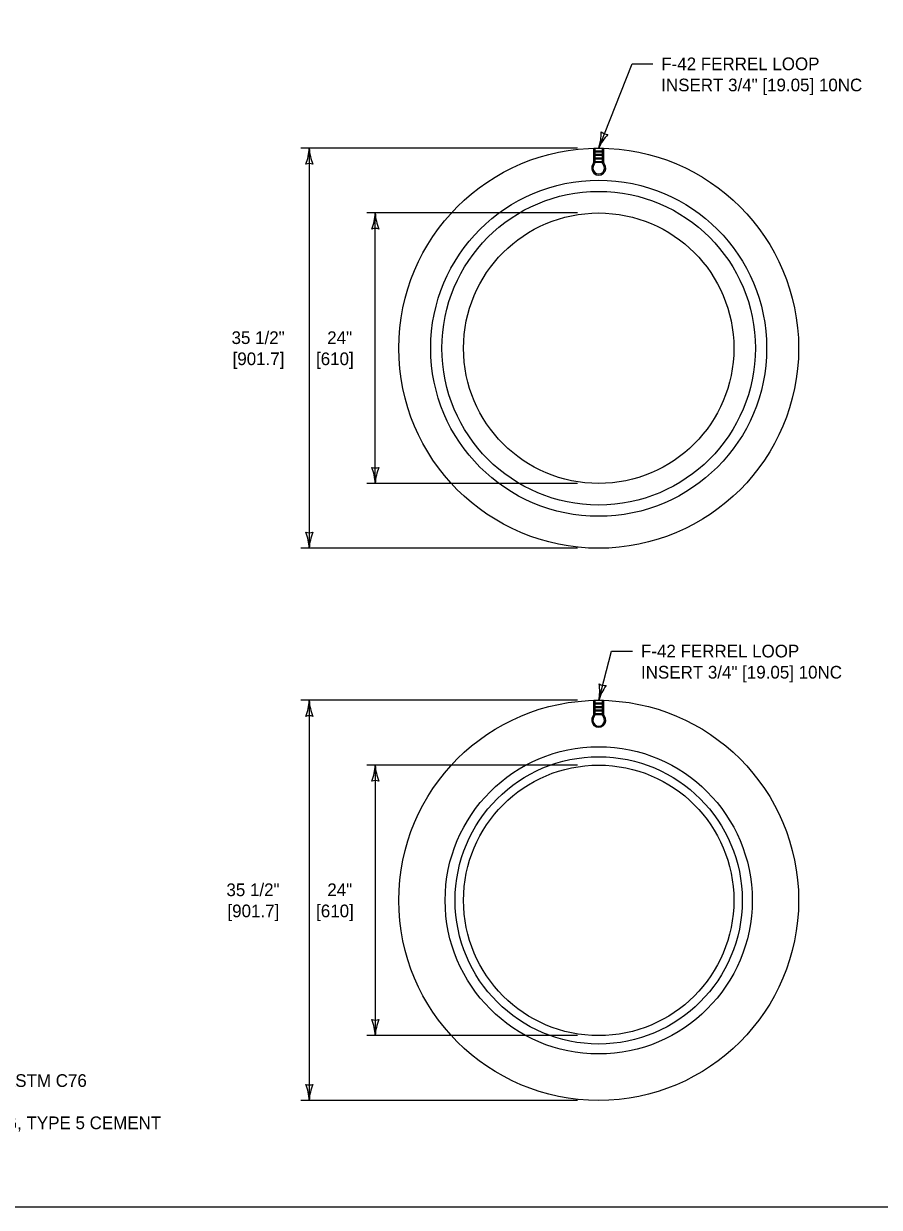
# Model space of a CAD drawing. Extents: x 49991.4 to 50021, y 49987.6 to 50011.4.
# Drawn here: x 50007.38 to 50011.44, y 49987.8 to 49993.4 of the extents above; entities that cross this region are included whole.
import ezdxf

# ---------------------------------------------------------------- set-up
doc = ezdxf.new("R2010")
doc.units = 0
for name, color, linetype in [('Level 1', 7, 'Continuous'), ('Level 2', 7, 'Continuous'), ('Level 3', 7, 'Continuous'), ('Level 4', 7, 'Continuous')]:
    doc.layers.add(name, color=color, linetype=linetype)

msp = doc.modelspace()

# ---------------------------------------------------------------- linework, layer by layer
at = {"layer": 'Level 1'}
msp.add_lwpolyline([(49999.3835, 49998.9992), (50016.7501, 49998.9992), (50016.7501, 49987.7988), (49999.3835, 49987.7988)], close=True, dxfattribs=at)
for centre, radius in [((50010.1074, 49991.8637), 0.9466), ((50010.1074, 49991.8637), 0.7953), ((50010.1074, 49991.8637), 0.7422), ((50010.1074, 49991.8637), 0.64), ((50010.1074, 49989.2512), 0.9466), ((50010.1074, 49989.2512), 0.7269), ((50010.1074, 49989.2512), 0.6798), ((50010.1074, 49989.2512), 0.64)]:
    msp.add_circle(centre, radius, dxfattribs=at)
at = {"layer": 'Level 3'}
for p, q in [((50010.0074, 49992.8104), (50008.6971, 49992.8104)), ((50008.7371, 49992.8104), (50008.7371, 49990.9171)), ((50010.0074, 49992.5037), (50009.0095, 49992.5037)), ((50009.0495, 49991.2237), (50009.0495, 49992.5037)), ((50010.0074, 49991.2237), (50009.0095, 49991.2237)), ((50010.0074, 49990.9171), (50008.6971, 49990.9171)), ((50010.0074, 49990.1978), (50008.6971, 49990.1978)), ((50008.7371, 49990.1978), (50008.7371, 49988.3045)), ((50010.0074, 49989.8912), (50009.0095, 49989.8912)), ((50009.0495, 49989.8912), (50009.0495, 49988.6112)), ((50010.0074, 49988.6112), (50009.0095, 49988.6112)), ((50010.0074, 49988.3045), (50008.6971, 49988.3045))]:
    msp.add_line(p, q, dxfattribs=at)
for points in [[(50010.1074, 49992.8104), (50010.2655, 49993.2093), (50010.3636, 49993.2093)], [(50010.1074, 49990.1978), (50010.1678, 49990.4307), (50010.2678, 49990.4307)]]:
    msp.add_lwpolyline(points, dxfattribs=at)
for centre, radius, start, end in [((50009.8868, 49992.8855), 0.233, 341.1989, 0.4487), ((50010.3105, 49992.72), 0.2223, 135.8276, 156.0111), ((50010.1546, 49992.9296), 0.0548, 230.5104, 266.2327), ((50008.5149, 49992.8196), 0.2223, 337.4389, 357.6225), ((50008.9698, 49992.8218), 0.233, 182.8102, 202.0601), ((50008.737, 49992.6822), 0.0548, 72.1218, 107.8441), ((50008.8274, 49992.513), 0.2223, 337.4389, 357.6225), ((50009.2822, 49992.5152), 0.233, 182.8102, 202.0601), ((50009.0495, 49992.3755), 0.0548, 72.1218, 107.8441), ((50009.0496, 49991.3519), 0.0548, 252.1218, 287.8441), ((50008.8168, 49991.2123), 0.233, 2.8102, 22.0601), ((50009.2717, 49991.2145), 0.2223, 157.4389, 177.6225), ((50008.7371, 49991.0453), 0.0548, 252.1218, 287.8441), ((50008.5044, 49990.9057), 0.233, 2.8102, 22.0601), ((50008.9592, 49990.9079), 0.2223, 157.4389, 177.6225), ((50009.8792, 49990.2451), 0.233, 348.2875, 7.5374), ((50010.1396, 49990.3219), 0.0548, 237.5991, 273.3214), ((50010.3201, 49990.1332), 0.2223, 142.9162, 163.0998), ((50008.5149, 49990.207), 0.2223, 337.4389, 357.6225), ((50008.9698, 49990.2092), 0.233, 182.8102, 202.0601), ((50008.737, 49990.0696), 0.0548, 72.1218, 107.8441), ((50008.8274, 49989.9004), 0.2223, 337.4389, 357.6225), ((50009.2822, 49989.9026), 0.233, 182.8102, 202.0601), ((50009.0495, 49989.763), 0.0548, 72.1218, 107.8441), ((50009.0496, 49988.7394), 0.0548, 252.1218, 287.8441), ((50008.8168, 49988.5998), 0.233, 2.8102, 22.0601), ((50009.2717, 49988.602), 0.2223, 157.4389, 177.6225), ((50008.7371, 49988.4327), 0.0548, 252.1218, 287.8441), ((50008.5044, 49988.2931), 0.233, 2.8102, 22.0601), ((50008.9592, 49988.2953), 0.2223, 157.4389, 177.6225)]:
    msp.add_arc(centre, radius, start, end, dxfattribs=at)
at = {"layer": 'Level 4'}
for p, q in [((50010.0851, 49992.748), (50010.0851, 49992.8104)), ((50010.0851, 49992.8104), (50010.1296, 49992.8104)), ((50010.0907, 49992.748), (50010.0907, 49992.8104)), ((50010.0907, 49992.7983), (50010.124, 49992.7983)), ((50010.124, 49992.8104), (50010.124, 49992.748)), ((50010.1296, 49992.8104), (50010.1296, 49992.748)), ((50010.0834, 49992.7405), (50010.084, 49992.7418)), ((50010.0886, 49992.7385), (50010.0891, 49992.7397)), ((50010.0902, 49992.7433), (50010.1245, 49992.7433)), ((50010.0907, 49992.7936), (50010.124, 49992.7936)), ((50010.0907, 49992.7815), (50010.124, 49992.7815)), ((50010.0907, 49992.7768), (50010.124, 49992.7768)), ((50010.0907, 49992.7648), (50010.124, 49992.7648)), ((50010.0907, 49992.7601), (50010.124, 49992.7601)), ((50010.0907, 49992.748), (50010.124, 49992.748)), ((50010.1261, 49992.7385), (50010.1256, 49992.7397)), ((50010.1313, 49992.7405), (50010.1308, 49992.7418)), ((50010.0851, 49990.1354), (50010.0851, 49990.1978)), ((50010.0851, 49990.1978), (50010.1296, 49990.1978)), ((50010.0907, 49990.1354), (50010.0907, 49990.1978)), ((50010.0907, 49990.1857), (50010.124, 49990.1857)), ((50010.0907, 49990.181), (50010.124, 49990.181)), ((50010.0907, 49990.169), (50010.124, 49990.169)), ((50010.0907, 49990.1643), (50010.124, 49990.1643)), ((50010.124, 49990.1978), (50010.124, 49990.1354)), ((50010.1296, 49990.1978), (50010.1296, 49990.1354)), ((50010.0834, 49990.128), (50010.084, 49990.1292)), ((50010.0886, 49990.1259), (50010.0891, 49990.1272)), ((50010.0902, 49990.1307), (50010.1245, 49990.1307)), ((50010.0907, 49990.1522), (50010.124, 49990.1522)), ((50010.0907, 49990.1475), (50010.124, 49990.1475)), ((50010.0907, 49990.1354), (50010.124, 49990.1354)), ((50010.1261, 49990.1259), (50010.1256, 49990.1272)), ((50010.1313, 49990.128), (50010.1308, 49990.1292))]:
    msp.add_line(p, q, dxfattribs=at)
for centre, radius, start, end in [((50010.068, 49992.7467), 0.0167, 321.9927, 338.1986), ((50010.0685, 49992.748), 0.0167, 338.1986, 0), ((50010.0685, 49992.748), 0.0222, 338.1986, 0), ((50010.1463, 49992.748), 0.0222, 180, 201.8014), ((50010.1463, 49992.748), 0.0167, 180, 201.8014), ((50010.1468, 49992.7467), 0.0167, 201.8014, 218.0073), ((50010.1074, 49992.7159), 0.0333, 141.9927, 38.0073), ((50010.1074, 49992.7159), 0.0278, 141.9927, 38.0073), ((50010.068, 49992.7467), 0.0222, 321.9927, 338.1986), ((50010.1468, 49992.7467), 0.0222, 201.8014, 218.0073), ((50010.1074, 49990.1034), 0.0333, 141.9927, 38.0073), ((50010.1074, 49990.1034), 0.0278, 141.9927, 38.0073), ((50010.068, 49990.1342), 0.0167, 321.9927, 338.1986), ((50010.0685, 49990.1354), 0.0167, 338.1986, 0), ((50010.068, 49990.1342), 0.0222, 321.9927, 338.1986), ((50010.0685, 49990.1354), 0.0222, 338.1986, 0), ((50010.1463, 49990.1354), 0.0222, 180, 201.8014), ((50010.1468, 49990.1342), 0.0222, 201.8014, 218.0073), ((50010.1463, 49990.1354), 0.0167, 180, 201.8014), ((50010.1468, 49990.1342), 0.0167, 201.8014, 218.0073)]:
    msp.add_arc(centre, radius, start, end, dxfattribs=at)

# ---------------------------------------------------------------- texts
at = {"layer": 'Level 2'}
for s, p in [('F-42 FERREL LOOP ', (50010.4036, 49993.1793)), ('INSERT 3/4" [19.05] 10NC', (50010.4036, 49993.0793)), ('35 1/2"', (50008.3691, 49991.8837)), ('[901.7]', (50008.3741, 49991.7837)), ('F-42 FERREL LOOP ', (50010.3078, 49990.4007)), ('INSERT 3/4" [19.05] 10NC', (50010.3078, 49990.3007)), ('35 1/2"', (50008.3448, 49989.2712)), ('[901.7]', (50008.3498, 49989.1712)), ('PRODUCED PER ASTM C76', (50006.6227, 49988.3686)), ('CL5 REINFORCING, TYPE 5 CEMENT', (50006.6227, 49988.1686))]:
    msp.add_text(s, height=0.06, dxfattribs=at).set_placement(p)
for s, p in [('24"', (50008.822, 49991.8837)), ('[610]', (50008.7691, 49991.7837)), ('24"', (50008.8225, 49989.2712)), ('[610]', (50008.7695, 49989.1712))]:
    msp.add_text(s, height=0.06, rotation=360, dxfattribs=at).set_placement(p)

doc.saveas('drawing.dxf')
